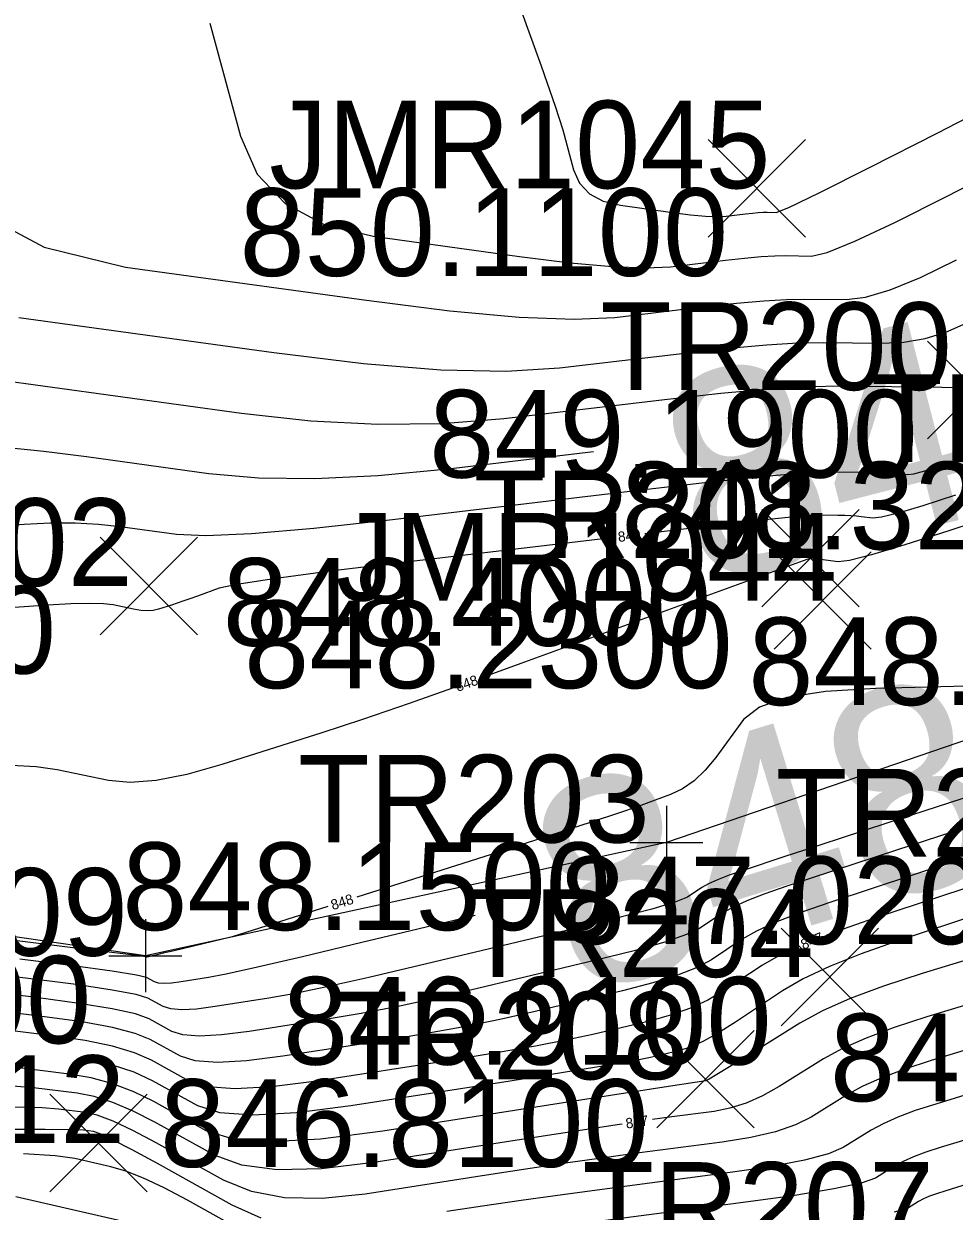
# Model space of a CAD drawing. Extents: x 1654928 to 1810050, y 486881 to 626330.
# Drawn here: x 1801355.05 to 1801367.8, y 489789.91 to 489806.17 of the extents above; entities that cross this region are included whole.
import ezdxf

# ---------------------------------------------------------------- set-up
doc = ezdxf.new("R2010")
doc.units = 0
for name, color, linetype in [('DT_X_Contour_Major', 7, 'Continuous'), ('DT_X_Contour_Minor', 7, 'Continuous'), ('SV_X_Random_Point', 7, 'Continuous'), ('SV_X_Shot_Marker', 7, 'Continuous'), ('SV_X_Text_Elevation', 7, 'Continuous'), ('SV_X_Text_Name', 7, 'Continuous'), ('SV_X_Top_of_Bank', 7, 'Continuous')]:
    doc.layers.add(name, color=color, linetype=linetype)

msp = doc.modelspace()

# ---------------------------------------------------------------- linework, layer by layer
at = {"layer": 'DT_X_Contour_Major'}
for points in [[(1801361.862, 489806.377), (1801362.145, 489805.595), (1801362.337, 489805.044), (1801362.438, 489804.722), (1801362.586, 489804.173), (1801362.669, 489803.988), (1801362.803, 489803.845), (1801362.991, 489803.745), (1801363.232, 489803.687), (1801363.944, 489803.588), (1801364.19, 489803.558), (1801364.394, 489803.539), (1801364.556, 489803.533), (1801364.677, 489803.538), (1801364.944, 489803.57), (1801365.037, 489803.58), (1801365.117, 489803.587), (1801365.184, 489803.591), (1801365.237, 489803.592), (1801365.362, 489803.59), (1801365.535, 489803.658), (1801365.962, 489803.862), (1801366.642, 489804.204), (1801367.576, 489804.681), (1801370.403, 489806.138)], [(1801362.859, 489800.31), (1801360.868, 489800.074), (1801359.907, 489799.98), (1801359.041, 489799.938), (1801358.269, 489799.948), (1801357.592, 489800.009), (1801355.913, 489800.241), (1801355.329, 489800.315), (1801354.837, 489800.363)], [(1801368.514, 489794.103), (1801367.041, 489793.617), (1801366.527, 489793.437), (1801366.091, 489793.262), (1801365.732, 489793.093), (1801365.45, 489792.929), (1801364.804, 489792.499), (1801364.573, 489792.354), (1801364.367, 489792.24), (1801364.186, 489792.158), (1801364.029, 489792.108), (1801363.643, 489792.016), (1801363.414, 489791.97), (1801363.017, 489791.9), (1801362.451, 489791.808), (1801361.718, 489791.692), (1801359.537, 489791.352), (1801358.793, 489791.256), (1801358.195, 489791.224), (1801357.743, 489791.257), (1801357.438, 489791.353), (1801356.82, 489791.695), (1801356.567, 489791.814), (1801356.273, 489791.912), (1801355.987, 489791.98)], [(1801361.24, 489793.958), (1801359.686, 489793.588), (1801358.875, 489793.396), (1801358.255, 489793.252), (1801357.826, 489793.157), (1801357.588, 489793.111), (1801357.21, 489793.052), (1801357.081, 489793.035), (1801356.977, 489793.03), (1801356.899, 489793.035), (1801356.846, 489793.052), (1801356.738, 489793.111), (1801356.6, 489793.144), (1801356.264, 489793.196), (1801355.732, 489793.269), (1801355.003, 489793.361)], [(1801368.169, 489790.953), (1801367.609, 489790.783), (1801367.413, 489790.719), (1801367.244, 489790.656), (1801367.103, 489790.593), (1801366.989, 489790.53), (1801366.721, 489790.364), (1801366.528, 489790.296), (1801366.151, 489790.216), (1801365.589, 489790.123), (1801364.842, 489790.019), (1801362.605, 489789.726)], [(1801358.2, 489789.56), (1801357.297, 489790.06), (1801356.977, 489790.229), (1801356.696, 489790.362), (1801356.453, 489790.459), (1801356.248, 489790.52), (1801355.754, 489790.633), (1801355.486, 489790.67), (1801355.053, 489790.696)]]:
    msp.add_lwpolyline(points, dxfattribs=at)
at = {"layer": 'DT_X_Contour_Minor'}
for points in [[(1801357.605, 489806.182), (1801358.023, 489804.634), (1801358.254, 489804.113), (1801358.634, 489803.711), (1801359.163, 489803.428), (1801359.841, 489803.264), (1801361.848, 489802.987), (1801362.541, 489802.9), (1801363.117, 489802.847), (1801363.575, 489802.829), (1801363.915, 489802.845), (1801364.666, 489802.934), (1801364.929, 489802.963), (1801365.155, 489802.983), (1801365.343, 489802.995), (1801365.493, 489802.997), (1801365.845, 489802.992), (1801366.06, 489803.042), (1801366.442, 489803.195), (1801366.99, 489803.451), (1801367.706, 489803.811), (1801369.835, 489804.908)], [(1801354.466, 489803.576), (1801355.336, 489803.111), (1801356.451, 489802.841), (1801359.752, 489802.385), (1801360.893, 489802.242), (1801361.84, 489802.156), (1801362.593, 489802.126), (1801363.154, 489802.152), (1801364.389, 489802.299), (1801364.821, 489802.347), (1801365.192, 489802.38), (1801365.502, 489802.398), (1801365.749, 489802.402), (1801366.328, 489802.394), (1801366.585, 489802.426), (1801366.922, 489802.528), (1801367.339, 489802.699), (1801367.835, 489802.941)], [(1801354.987, 489802.152), (1801358.481, 489801.669), (1801359.708, 489801.52), (1801360.769, 489801.435), (1801361.664, 489801.415), (1801362.392, 489801.459), (1801364.111, 489801.663), (1801364.714, 489801.73), (1801365.23, 489801.776), (1801365.661, 489801.802), (1801366.005, 489801.808), (1801366.811, 489801.796), (1801367.11, 489801.81), (1801367.402, 489801.86), (1801367.687, 489801.947), (1801367.965, 489802.071)], [(1801354.582, 489801.313), (1801355.45, 489801.197), (1801358.037, 489800.839), (1801358.989, 489800.734), (1801359.905, 489800.687), (1801360.785, 489800.698), (1801361.63, 489800.767), (1801363.834, 489801.028), (1801364.606, 489801.113), (1801365.268, 489801.172), (1801365.819, 489801.205), (1801366.262, 489801.213), (1801367.634, 489801.194), (1801367.881, 489801.193)], [(1801367.916, 489800.205), (1801367.619, 489800.109), (1801367.395, 489800.043), (1801367.244, 489800.005), (1801367.167, 489799.996), (1801367.06, 489800.01), (1801367.001, 489800.015), (1801366.901, 489800.019), (1801366.762, 489800.023), (1801366.584, 489800.026), (1801366.055, 489800.033), (1801365.733, 489800.018), (1801365.163, 489799.967), (1801364.345, 489799.88), (1801363.279, 489799.757), (1801360.106, 489799.381), (1801359.029, 489799.262), (1801358.177, 489799.189), (1801357.55, 489799.161), (1801357.148, 489799.179), (1801356.376, 489799.285), (1801356.077, 489799.317), (1801355.758, 489799.333), (1801355.419, 489799.332), (1801355.06, 489799.315), (1801354.077, 489799.248)], [(1801369.533, 489799.82), (1801367.726, 489799.228), (1801367.124, 489799.035), (1801366.67, 489798.9), (1801366.365, 489798.823), (1801366.21, 489798.805), (1801365.831, 489798.854), (1801361.866, 489797.409), (1801361.325, 489797.214)], [(1801367.821, 489799.716), (1801367.371, 489799.572), (1801367.032, 489799.471), (1801366.805, 489799.414), (1801366.688, 489799.4), (1801366.527, 489799.421), (1801366.461, 489799.428), (1801366.386, 489799.434), (1801366.302, 489799.438), (1801366.207, 489799.44), (1801365.943, 489799.444), (1801365.71, 489799.428), (1801365.21, 489799.377), (1801364.442, 489799.29), (1801363.563, 489799.188)], [(1801363.146, 489799.138), (1801360.29, 489798.8), (1801359.253, 489798.674), (1801358.481, 489798.572), (1801357.973, 489798.495), (1801357.73, 489798.442), (1801357.435, 489798.334), (1801357.329, 489798.296), (1801357.235, 489798.263), (1801357.079, 489798.211), (1801356.9, 489798.154), (1801356.829, 489798.138), (1801356.748, 489798.133), (1801356.658, 489798.138), (1801356.558, 489798.155), (1801356.28, 489798.213), (1801356.146, 489798.229), (1801355.952, 489798.233), (1801355.699, 489798.227), (1801355.385, 489798.209), (1801354.468, 489798.146)], [(1801370.296, 489797.161), (1801366.727, 489797.07), (1801366.04, 489797.028), (1801365.509, 489796.944), (1801365.133, 489796.815), (1801364.914, 489796.643), (1801364.537, 489796.126), (1801364.391, 489795.949), (1801364.239, 489795.805), (1801364.08, 489795.693), (1801363.914, 489795.615), (1801363.46, 489795.45), (1801363.214, 489795.364), (1801362.815, 489795.232), (1801362.263, 489795.054), (1801361.558, 489794.828), (1801359.62, 489794.211)], [(1801360.929, 489797.072), (1801360.335, 489796.863), (1801359.695, 489796.644), (1801359.14, 489796.463), (1801357.77, 489796.027), (1801357.288, 489795.891), (1801356.868, 489795.809), (1801356.511, 489795.782), (1801356.216, 489795.81), (1801355.512, 489795.956), (1801355.223, 489795.998), (1801354.882, 489796.013)], [(1801370.17, 489796.297), (1801367.722, 489795.499), (1801366.892, 489795.228), (1801366.24, 489795.015), (1801365.765, 489794.86), (1801365.467, 489794.762), (1801364.909, 489794.578), (1801364.717, 489794.511), (1801364.559, 489794.45), (1801364.434, 489794.393), (1801364.343, 489794.342), (1801364.147, 489794.211), (1801363.988, 489794.145), (1801363.659, 489794.047), (1801363.159, 489793.917), (1801362.49, 489793.753), (1801360.478, 489793.273), (1801359.783, 489793.11), (1801359.207, 489792.982), (1801358.751, 489792.887), (1801358.414, 489792.827), (1801357.675, 489792.712), (1801357.423, 489792.679), (1801357.221, 489792.669), (1801357.068, 489792.68), (1801356.964, 489792.712), (1801356.755, 489792.828), (1801356.593, 489792.878), (1801356.266, 489792.939), (1801355.773, 489793.013), (1801355.115, 489793.099), (1801353.139, 489793.344)], [(1801368.409, 489795.311), (1801367.771, 489795.103), (1801367.221, 489794.923), (1801366.759, 489794.772), (1801365.51, 489794.36), (1801365.208, 489794.255), (1801364.959, 489794.159), (1801364.763, 489794.07), (1801364.62, 489793.989), (1801364.311, 489793.783), (1801364.134, 489793.698), (1801363.836, 489793.596), (1801363.416, 489793.477), (1801362.875, 489793.342), (1801361.269, 489792.959), (1801360.69, 489792.825), (1801360.16, 489792.711), (1801359.676, 489792.617), (1801359.24, 489792.543), (1801358.141, 489792.372), (1801357.766, 489792.324), (1801357.464, 489792.308), (1801357.236, 489792.324), (1801357.083, 489792.372), (1801356.771, 489792.545), (1801356.587, 489792.612), (1801356.268, 489792.683), (1801355.815, 489792.757), (1801355.227, 489792.837), (1801353.48, 489793.053)], [(1801367.781, 489794.693), (1801366.11, 489794.142), (1801365.698, 489793.999), (1801365.358, 489793.867), (1801365.091, 489793.746), (1801364.897, 489793.636), (1801364.475, 489793.355), (1801364.281, 489793.25), (1801364.013, 489793.144), (1801363.673, 489793.037), (1801363.259, 489792.93), (1801362.06, 489792.645), (1801361.598, 489792.54), (1801361.112, 489792.441), (1801360.601, 489792.347), (1801360.066, 489792.259), (1801358.606, 489792.032), (1801358.108, 489791.968), (1801357.708, 489791.947), (1801357.405, 489791.968), (1801357.201, 489792.033), (1801356.787, 489792.262), (1801356.58, 489792.346), (1801356.27, 489792.426), (1801355.856, 489792.502), (1801355.339, 489792.574), (1801353.822, 489792.762)], [(1801368.224, 489794.423), (1801366.71, 489793.924), (1801366.188, 489793.743), (1801366.051, 489793.69)], [(1801359.22, 489794.084), (1801357.911, 489793.667), (1801357.117, 489793.478), (1801356.967, 489793.442), (1801356.858, 489793.417), (1801356.79, 489793.401), (1801356.763, 489793.395), (1801356.745, 489793.392), (1801356.738, 489793.391), (1801356.733, 489793.391), (1801356.73, 489793.391), (1801356.727, 489793.392), (1801356.722, 489793.395), (1801356.606, 489793.41), (1801356.262, 489793.453), (1801355.691, 489793.524), (1801354.891, 489793.623)], [(1801365.662, 489793.532), (1801365.42, 489793.422), (1801365.174, 489793.282), (1801364.639, 489792.927), (1801364.427, 489792.802), (1801364.19, 489792.692), (1801363.929, 489792.598), (1801363.644, 489792.519), (1801362.851, 489792.33), (1801362.506, 489792.255), (1801362.064, 489792.171), (1801361.526, 489792.078), (1801360.892, 489791.976), (1801359.072, 489791.692), (1801358.45, 489791.612), (1801357.951, 489791.586), (1801357.574, 489791.613), (1801357.32, 489791.693), (1801356.803, 489791.978), (1801356.574, 489792.08), (1801356.272, 489792.169), (1801355.897, 489792.246), (1801355.451, 489792.312), (1801354.164, 489792.472)], [(1801368.877, 489793.627), (1801367.364, 489793.166), (1801366.834, 489792.994), (1801366.378, 489792.823), (1801365.996, 489792.653), (1801365.687, 489792.484), (1801364.964, 489792.035), (1801364.725, 489791.888), (1801364.551, 489791.782), (1801364.443, 489791.718), (1801364.4, 489791.696), (1801364.246, 489791.673), (1801363.888, 489791.617), (1801363.298, 489791.525), (1801362.475, 489791.397), (1801359.973, 489791.007), (1801359.119, 489790.898), (1801358.431, 489790.862), (1801357.91, 489790.901), (1801357.556, 489791.013), (1801356.836, 489791.412), (1801356.561, 489791.547), (1801356.275, 489791.655), (1801355.98, 489791.735), (1801355.675, 489791.788), (1801354.847, 489791.89)], [(1801368.7, 489792.958), (1801367.426, 489792.57), (1801366.979, 489792.425), (1801366.595, 489792.281), (1801366.272, 489792.138), (1801366.013, 489791.996), (1801365.403, 489791.618), (1801365.176, 489791.49), (1801364.951, 489791.391), (1801364.729, 489791.32), (1801364.511, 489791.277), (1801363.931, 489791.201), (1801363.666, 489791.164)], [(1801368.523, 489792.29), (1801367.487, 489791.974), (1801367.124, 489791.856), (1801366.811, 489791.739), (1801366.549, 489791.623), (1801366.338, 489791.507), (1801365.842, 489791.2), (1801365.627, 489791.092), (1801365.351, 489790.999), (1801365.016, 489790.921), (1801364.621, 489790.858), (1801363.489, 489790.709), (1801363.039, 489790.648), (1801362.54, 489790.577), (1801361.992, 489790.495), (1801361.394, 489790.403), (1801359.733, 489790.144), (1801359.145, 489790.083), (1801358.625, 489790.094), (1801358.175, 489790.178), (1801357.793, 489790.334), (1801356.868, 489790.845), (1801356.548, 489791.015), (1801356.279, 489791.142), (1801356.063, 489791.224), (1801355.899, 489791.263), (1801355.531, 489791.309), (1801355.309, 489791.324), (1801354.918, 489791.334)], [(1801363.251, 489791.103), (1801363.214, 489791.097), (1801361.935, 489790.9), (1801359.853, 489790.576), (1801359.132, 489790.49), (1801358.528, 489790.478), (1801358.043, 489790.539), (1801357.675, 489790.673), (1801356.852, 489791.129), (1801356.554, 489791.281), (1801356.277, 489791.398), (1801356.021, 489791.48), (1801355.787, 489791.525), (1801355.189, 489791.6), (1801354.902, 489791.624)], [(1801368.346, 489791.622), (1801367.548, 489791.378), (1801367.268, 489791.288), (1801367.028, 489791.197), (1801366.826, 489791.108), (1801366.663, 489791.019), (1801366.282, 489790.782), (1801366.077, 489790.694), (1801365.751, 489790.607), (1801365.302, 489790.522), (1801364.732, 489790.439), (1801363.047, 489790.217), (1801362.436, 489790.136), (1801361.867, 489790.057), (1801361.339, 489789.98), (1801360.853, 489789.906)], [(1801358.307, 489789.816), (1801357.912, 489789.994), (1801356.885, 489790.562), (1801356.541, 489790.749), (1801356.281, 489790.885), (1801356.104, 489790.969), (1801356.011, 489791.001), (1801355.873, 489791.018), (1801355.715, 489791.024), (1801355.347, 489791.027), (1801354.767, 489791.029)], [(1801367.992, 489790.285), (1801367.671, 489790.187), (1801367.558, 489790.15), (1801367.461, 489790.114), (1801367.38, 489790.078), (1801367.314, 489790.042), (1801367.16, 489789.946), (1801366.979, 489789.898)], [(1801356.675, 489789.709), (1801354.946, 489790.106)]]:
    msp.add_lwpolyline(points, dxfattribs=at)
at = {"layer": 'SV_X_Random_Point'}
for p, q in [((1801364.43, 489803.252), (1801365.763, 489804.587)), ((1801364.43, 489804.587), (1801365.763, 489803.252)), ((1801367.434, 489800.489), (1801368.768, 489801.824)), ((1801367.434, 489801.824), (1801368.768, 489800.489)), ((1801365.164, 489798.187), (1801366.498, 489799.522)), ((1801365.164, 489799.522), (1801366.498, 489798.187)), ((1801356.103, 489797.805), (1801357.436, 489799.14)), ((1801356.103, 489799.14), (1801357.436, 489797.805)), ((1801365.333, 489797.606), (1801366.666, 489798.941)), ((1801365.333, 489798.941), (1801366.666, 489797.606)), ((1801365.431, 489792.451), (1801366.765, 489793.786)), ((1801365.431, 489793.786), (1801366.765, 489792.451)), ((1801363.728, 489791.05), (1801365.061, 489792.385)), ((1801363.728, 489792.385), (1801365.061, 489791.05)), ((1801355.411, 489790.176), (1801356.744, 489791.511)), ((1801355.411, 489791.511), (1801356.744, 489790.176))]:
    msp.add_line(p, q, dxfattribs=at)
at = {"layer": 'SV_X_Shot_Marker'}
for p, q in [((1801363.859, 489795.46), (1801363.859, 489794.46)), ((1801363.359, 489794.96), (1801364.359, 489794.96)), ((1801363.859, 489794.96), (1801363.859, 489794.96)), ((1801356.721, 489793.909), (1801356.721, 489792.909)), ((1801356.221, 489793.409), (1801357.221, 489793.409)), ((1801356.721, 489793.409), (1801356.721, 489793.409))]:
    msp.add_line(p, q, dxfattribs=at)
at = {"layer": 'SV_X_Top_of_Bank'}
msp.add_lwpolyline([(1801422.074, 489809.374), (1801419.071, 489811.095), (1801415.847, 489811.951), (1801411.348, 489810.567), (1801392.1, 489806.2), (1801386.944, 489805.19), (1801377.801, 489798.251), (1801372.871, 489798.042), (1801363.859, 489794.96), (1801356.721, 489793.409), (1801350.319, 489794.339), (1801339.193, 489795.613), (1801330.88, 489795.172), (1801318.326, 489796.108)], dxfattribs=at)

# ---------------------------------------------------------------- texts
at = {"layer": 'DT_X_Contour_Major'}
for s, rotation, p in [('849', 14.4598, (1801364.287, 489798.454)), ('848', 17.0117, (1801362.611, 489792.833))]:
    msp.add_text(s, height=2.8, rotation=rotation, dxfattribs=at).set_placement(p)
at = {"layer": 'DT_X_Contour_Minor'}
for s, rotation, p in [('849', 6.7267, (1801363.203, 489799.075)), ('848', 19.6981, (1801361, 489797.022)), ('848', 17.6568, (1801359.288, 489794.032)), ('847', 22.0321, (1801365.734, 489793.489)), ('847', 8.4004, (1801363.311, 489791.041))]:
    msp.add_text(s, height=0.14, rotation=rotation, dxfattribs=at).set_placement(p)
at = {"layer": 'SV_X_Text_Elevation'}
for s, p in [('850.1100', (1801358.011, 489802.719)), ('849.1900', (1801360.609, 489799.957)), ('848.3200', (1801363.242, 489798.973)), ('848.4000', (1801357.781, 489797.654)), ('848.6300', (1801348.805, 489797.273)), ('848.2300', (1801358.073, 489797.073)), ('848.2200', (1801364.981, 489796.842)), ('848.1500', (1801356.405, 489793.76)), ('847.0200', (1801362.399, 489793.568)), ('848.2100', (1801349.286, 489792.209)), ('846.9100', (1801358.606, 489791.918)), ('845.8300', (1801366.099, 489791.416)), ('846.8100', (1801356.922, 489790.517))]:
    msp.add_text(s, height=1.2, dxfattribs=at).set_placement(p)
at = {"layer": 'SV_X_Text_Name'}
for s, p in [('JMR1045', (1801358.417, 489803.919)), ('TR200', (1801362.952, 489801.157)), ('TR199', (1801366.663, 489800.173)), ('TR201', (1801361.219, 489798.854)), ('TR202', (1801351.734, 489798.473)), ('JMR1044', (1801359.33, 489798.273)), ('TR203', (1801358.814, 489794.96)), ('TR205', (1801365.357, 489794.768)), ('TR209', (1801351.667, 489793.409)), ('TR204', (1801361.062, 489793.118)), ('TR208', (1801359.34, 489791.717)), ('TR212', (1801351.628, 489790.844)), ('TR207', (1801362.708, 489789.382))]:
    msp.add_text(s, height=1.2, dxfattribs=at).set_placement(p)

doc.saveas('drawing.dxf')
